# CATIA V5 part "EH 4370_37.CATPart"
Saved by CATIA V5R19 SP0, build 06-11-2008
Definition: EH 4370_37
Nomenclature: EH 4370_37
Description: PART--DESC
Material "Plastic": density 1200 kg/m3, Young's modulus 2.2e+09 Pa, Poisson ratio 0.38, thermal expansion 6.84e-05 1/K
Bounding box of the stored display mesh (mm): x 113.55 to 126.45, y 103.559 to 116.441, z -57 to -48
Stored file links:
  G:\UTB\Kombinované\Bakalářská práce\Catia\FORMA\EH 4370_37.CATPart
  D:\Aplikace\CATIA\Nová složka\win_b64\startup\materials\Catalog.CATMaterial
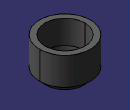
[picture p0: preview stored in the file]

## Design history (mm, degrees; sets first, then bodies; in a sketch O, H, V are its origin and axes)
Body1 "EH 4370_37" (main body)
  Solid1: solid without history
